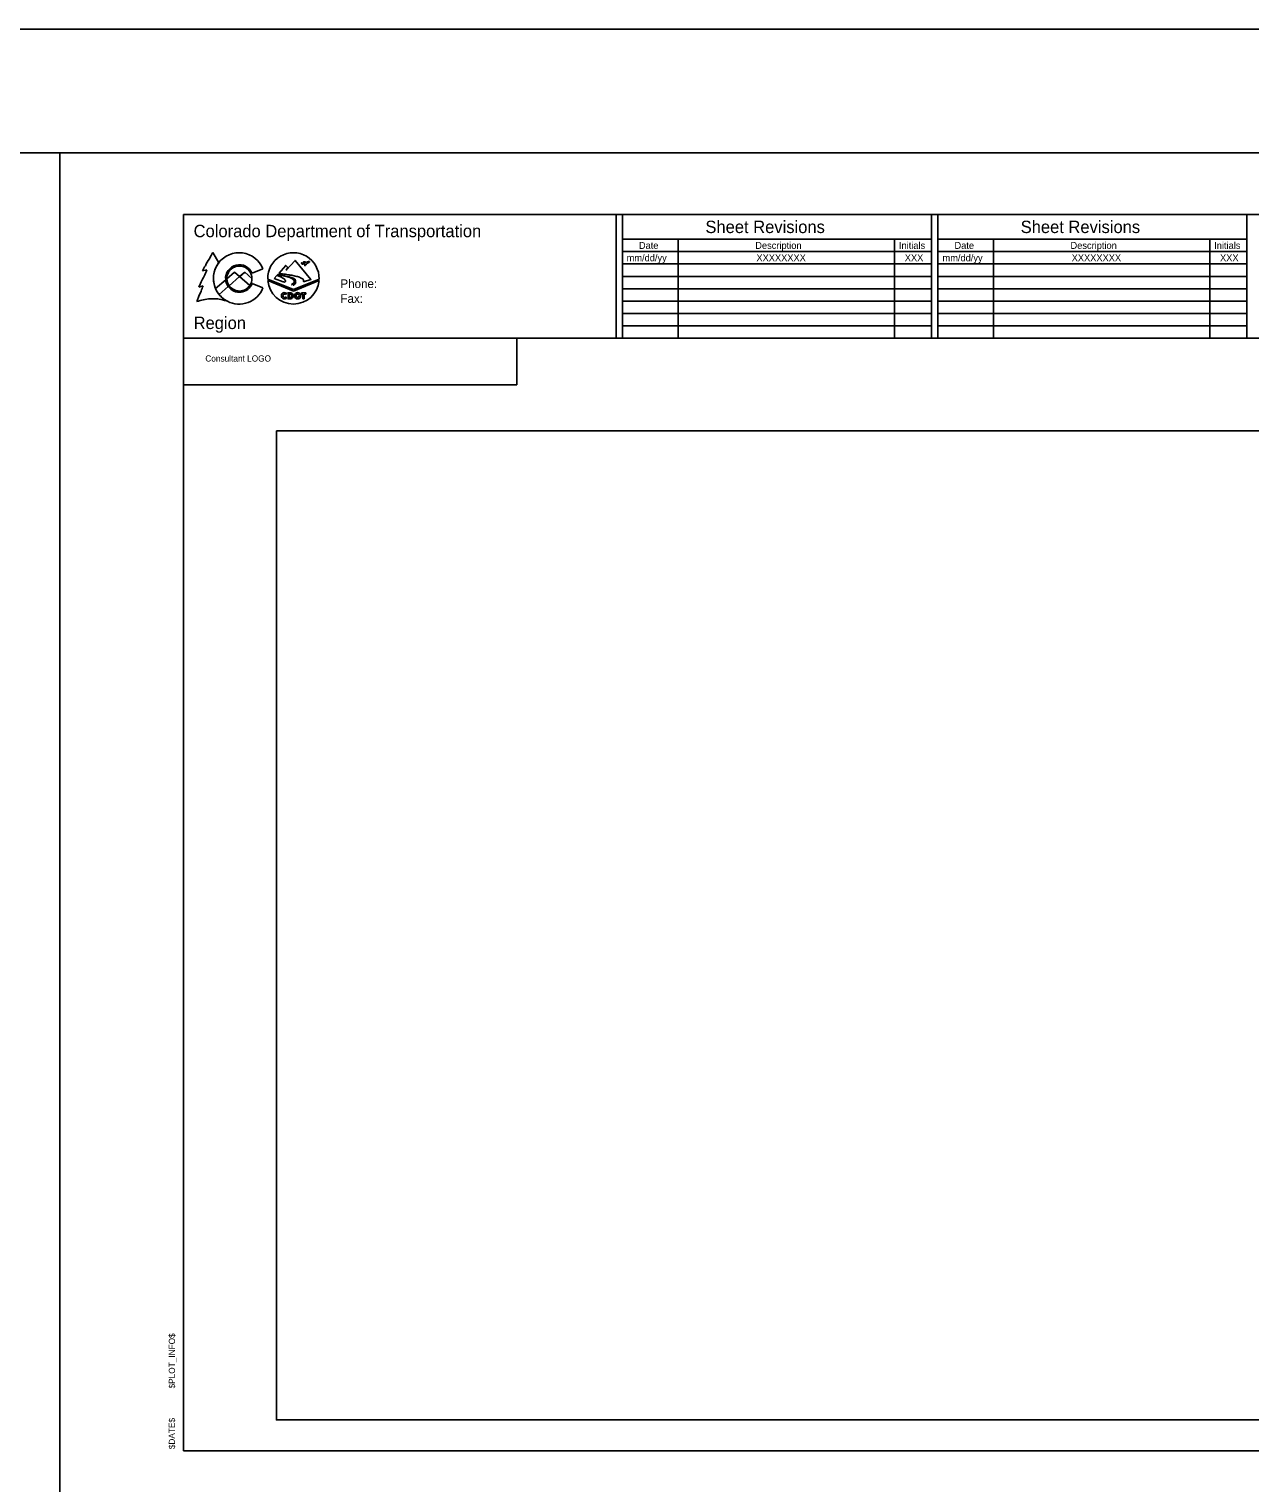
# Model space of a CAD drawing. Extents: x 0 to 3, y 0 to 2.
# Drawn here: x 1.521 to 2.344, y 1.02 to 2 of the extents above; entities that cross this region are included whole.
import ezdxf

# ---------------------------------------------------------------- set-up
doc = ezdxf.new("R2010")
doc.units = 0
for name, color, linetype in [('DRAFT_Information-No Plot', 7, 'Continuous'), ('SHEET_Lines', 7, 'Continuous'), ('SHEET_North Arrow', 7, 'Continuous'), ('SHEET_Plot Boundary', 7, 'Continuous'), ('SHEET_Text-Border Info', 7, 'Continuous')]:
    doc.layers.add(name, color=color, linetype=linetype)

msp = doc.modelspace()

# ---------------------------------------------------------------- linework, layer by layer
at = {"layer": 'DRAFT_Information-No Plot'}
msp.add_line((1.625, 1.79167), (1.625, 1.79167), dxfattribs=at)
msp.add_lwpolyline([(1.6875, 1.72917), (2.85417, 1.72917), (2.85417, 1.0625), (1.6875, 1.0625)], close=True, dxfattribs=at)
at = {"layer": 'SHEET_Lines'}
for p, q in [((1.54167, 1.91667), (1.54167, 0.08333)), ((1.625, 1.79167), (1.625, 1.875)), ((1.625, 1.875), (2.91667, 1.875)), ((1.91667, 1.875), (1.91667, 1.79167)), ((1.92083, 1.875), (1.92083, 1.79167)), ((2.12917, 1.875), (2.12917, 1.79167)), ((2.13333, 1.875), (2.13333, 1.79167)), ((2.34167, 1.875), (2.34167, 1.79167)), ((1.92083, 1.85833), (2.12917, 1.85833)), ((1.95833, 1.79167), (1.95833, 1.85833)), ((2.10417, 1.79167), (2.10417, 1.85833)), ((2.13333, 1.85833), (2.34167, 1.85833)), ((2.17083, 1.79167), (2.17083, 1.85833)), ((2.31667, 1.79167), (2.31667, 1.85833)), ((1.92083, 1.85), (2.12917, 1.85)), ((2.13333, 1.85), (2.34167, 1.85)), ((1.92083, 1.84167), (2.12917, 1.84167)), ((1.92083, 1.83333), (2.12917, 1.83333)), ((2.13333, 1.84167), (2.34167, 1.84167)), ((2.13333, 1.83333), (2.34167, 1.83333)), ((1.92083, 1.825), (2.12917, 1.825)), ((2.13333, 1.825), (2.34167, 1.825)), ((1.92083, 1.81667), (2.12917, 1.81667)), ((2.13333, 1.81667), (2.34167, 1.81667)), ((1.92083, 1.80833), (2.12917, 1.80833)), ((2.13333, 1.80833), (2.34167, 1.80833)), ((1.92083, 1.8), (2.12917, 1.8)), ((2.13333, 1.8), (2.34167, 1.8))]:
    msp.add_line(p, q, dxfattribs=at)
for points in [[(2.95833, 0.08333), (0.125, 0.08333), (0.125, 1.91667), (2.95833, 1.91667)], [(1.625, 1.79167), (1.84959, 1.79167), (1.84959, 1.76025), (1.625, 1.76025)]]:
    msp.add_lwpolyline(points, close=True, dxfattribs=at)
msp.add_lwpolyline([(2.55417, 1.79167), (1.625, 1.79167), (1.625, 1.04167), (2.91667, 1.04167), (2.91667, 1.79167), (2.69167, 1.79167)], dxfattribs=at)
at = {"layer": 'SHEET_Plot Boundary'}
for p, q in [((1.64467, 1.8493), (1.64867, 1.84245)), ((1.64061, 1.83769), (1.63782, 1.83706)), ((1.6593, 1.83614), (1.65414, 1.83166)), ((1.65414, 1.83161), (1.6593, 1.83609)), ((1.66277, 1.83313), (1.6557, 1.827)), ((1.6557, 1.827), (1.66277, 1.83313)), ((1.66277, 1.83313), (1.6593, 1.83614)), ((1.6593, 1.83609), (1.66277, 1.83308)), ((1.66622, 1.83613), (1.66277, 1.83313)), ((1.66277, 1.83308), (1.66622, 1.83608)), ((1.66962, 1.82719), (1.66277, 1.83313)), ((1.66277, 1.83313), (1.66962, 1.82719)), ((1.67104, 1.83194), (1.66622, 1.83613)), ((1.66622, 1.83608), (1.67104, 1.83189)), ((1.67117, 1.83542), (1.67848, 1.83834)), ((1.68606, 1.83182), (1.68788, 1.8339)), ((1.68834, 1.83442), (1.68856, 1.83467)), ((1.70703, 1.84177), (1.70561, 1.84145)), ((1.63818, 1.82697), (1.63533, 1.82609)), ((1.64652, 1.82505), (1.65336, 1.83098)), ((1.65336, 1.83098), (1.64652, 1.82505)), ((1.65507, 1.82645), (1.64891, 1.8211)), ((1.64891, 1.8211), (1.65507, 1.82645)), ((1.67849, 1.82552), (1.67119, 1.82842)), ((1.68172, 1.83148), (1.69902, 1.82442)), ((1.69902, 1.82343), (1.68178, 1.83046)), ((1.69216, 1.82967), (1.68606, 1.83182)), ((1.69808, 1.82766), (1.69773, 1.82781)), ((1.69921, 1.82728), (1.69882, 1.82746)), ((1.69902, 1.82442), (1.71632, 1.83148)), ((1.71627, 1.83046), (1.69902, 1.82343)), ((1.69382, 1.81944), (1.69453, 1.81876)), ((1.69455, 1.82166), (1.69383, 1.82099)), ((1.70451, 1.82135), (1.70451, 1.82223)), ((1.70451, 1.82223), (1.70733, 1.82223)), ((1.70547, 1.82135), (1.70451, 1.82135)), ((1.70547, 1.81812), (1.70547, 1.82135)), ((1.70637, 1.81812), (1.70547, 1.81812)), ((1.70733, 1.82135), (1.70637, 1.82135)), ((1.70637, 1.82135), (1.70637, 1.81812)), ((1.70733, 1.82223), (1.70733, 1.82135))]:
    msp.add_line(p, q, dxfattribs=at)
msp.add_lwpolyline([(0, 2), (3, 2), (3, 0), (0, 0)], close=True, dxfattribs=at)
for points in [[(1.68909, 1.83528), (1.6938, 1.84065), (1.69514, 1.83924), (1.69416, 1.8375), (1.7001, 1.84402), (1.71083, 1.8313), (1.70574, 1.82956)], [(1.69717, 1.81812), (1.6954, 1.81812), (1.6954, 1.82223), (1.69717, 1.82223)], [(1.69694, 1.82136), (1.69632, 1.82136), (1.69632, 1.81901), (1.69694, 1.81901)]]:
    msp.add_lwpolyline(points, dxfattribs=at)
for radius in [0.00212, 0.00114]:
    msp.add_circle((1.70183, 1.82022), radius, dxfattribs=at)
for centre, radius, start, end in [((1.66241, 1.83192), 0.01731, 21.75871, 203.38863), ((1.66243, 1.83193), 0.01732, 142.59022, 242.67381), ((1.69902, 1.83192), 0.01731, 358.51701, 181.48299), ((1.66259, 1.83189), 0.00928, 22.36058, 185.62032), ((1.66259, 1.83184), 0.00845, 0.35858, 181.56098), ((1.66241, 1.83192), 0.01731, 203.38863, 242.71912), ((1.66259, 1.83189), 0.00928, 185.62032, 215.87253), ((1.66259, 1.83189), 0.00845, 181.56098, 215.37659), ((1.66241, 1.83192), 0.01731, 242.71912, 338.26838), ((1.66259, 1.83189), 0.00928, 215.87253, 338.04863), ((1.66259, 1.83189), 0.00845, 215.37659, 326.23275), ((1.66259, 1.83189), 0.00845, 326.23275, 0.35858), ((1.69902, 1.83192), 0.01731, 184.84023, 355.15977), ((1.66243, 1.83193), 0.01732, 218.67794, 242.67381), ((1.66243, 1.83193), 0.01732, 218.67794, 242.67381), ((1.69299, 1.82022), 0.00212, 42.62362, 316.67791), ((1.69299, 1.82022), 0.00114, 42.62362, 316.67791), ((1.69687, 1.82019), 0.00118, 273.22356, 86.77644), ((1.69694, 1.82018), 0.00207, 276.24904, 83.75096)]:
    msp.add_arc(centre, radius, start, end, dxfattribs=at)
for points in [[(1.63782, 1.83706), (1.63965, 1.84048), (1.64234, 1.84523), (1.64467, 1.8493)], [(1.70561, 1.84145), (1.70507, 1.84144), (1.705, 1.84151), (1.7048, 1.84174), (1.70438, 1.84222), (1.70438, 1.84236), (1.70454, 1.84244), (1.70491, 1.84241), (1.70508, 1.84227), (1.70542, 1.84205), (1.70555, 1.84205), (1.70566, 1.84205), (1.70668, 1.84242)], [(1.70668, 1.84242), (1.70611, 1.84267), (1.70588, 1.84278), (1.70571, 1.84291), (1.70579, 1.843), (1.70605, 1.8431), (1.70624, 1.84315), (1.70645, 1.84313), (1.70665, 1.84308), (1.70704, 1.84296), (1.70766, 1.84275)], [(1.70766, 1.84275), (1.7084, 1.84304), (1.70903, 1.84325), (1.7093, 1.84333), (1.70954, 1.84337), (1.70976, 1.84335), (1.70985, 1.84326), (1.70984, 1.84305), (1.70971, 1.84287), (1.70906, 1.84249), (1.70815, 1.84209)], [(1.63533, 1.82609), (1.6364, 1.82856), (1.64015, 1.83645), (1.64061, 1.83769)], [(1.68788, 1.8339), (1.68865, 1.83367), (1.68929, 1.83345), (1.69035, 1.83303), (1.6915, 1.83239), (1.69243, 1.83177), (1.69301, 1.83132), (1.69347, 1.83074), (1.69363, 1.83044), (1.69367, 1.83023), (1.69357, 1.82985), (1.69332, 1.82963), (1.69318, 1.82954), (1.69281, 1.82944), (1.69254, 1.82953), (1.69235, 1.82961), (1.69216, 1.82967)], [(1.68856, 1.83467), (1.69311, 1.83374), (1.69705, 1.83258), (1.69872, 1.83182), (1.69977, 1.83103), (1.70046, 1.83008), (1.7001, 1.82824), (1.69921, 1.82728)], [(1.70574, 1.82956), (1.70596, 1.83017), (1.70565, 1.83114), (1.70374, 1.83241), (1.70099, 1.83333), (1.69787, 1.83401), (1.69554, 1.83442), (1.69162, 1.835), (1.68909, 1.83528)], [(1.70815, 1.84209), (1.70757, 1.84127), (1.70721, 1.84075), (1.7069, 1.84056), (1.7066, 1.84058), (1.70678, 1.8411), (1.70703, 1.84177)], [(1.63393, 1.81626), (1.63483, 1.81866), (1.63677, 1.82341), (1.63818, 1.82697)], [(1.69692, 1.83238), (1.6972, 1.83225), (1.69747, 1.8321), (1.69773, 1.83193), (1.69787, 1.83185), (1.698, 1.83177), (1.69819, 1.83165), (1.69838, 1.83152), (1.69857, 1.83138), (1.69866, 1.83131), (1.69874, 1.83124), (1.69885, 1.83115), (1.699, 1.831), (1.69914, 1.83083), (1.69926, 1.83066), (1.69934, 1.83052), (1.6994, 1.83042), (1.69943, 1.83032), (1.69944, 1.83026), (1.69947, 1.83018), (1.69949, 1.83008), (1.69952, 1.82994), (1.69953, 1.82965), (1.6995, 1.82936), (1.69946, 1.82922), (1.69941, 1.82908), (1.69928, 1.82882), (1.6991, 1.82858), (1.69888, 1.82836), (1.69865, 1.82815), (1.69851, 1.82802), (1.69837, 1.8279), (1.69822, 1.82778), (1.69808, 1.82766)], [(1.69882, 1.82746), (1.69936, 1.8279), (1.69993, 1.82858), (1.70014, 1.82901), (1.70003, 1.83031), (1.69984, 1.83058), (1.69941, 1.831), (1.69808, 1.83189), (1.69692, 1.83238)], [(1.65448, 1.81654), (1.65199, 1.81731), (1.64798, 1.81806), (1.64504, 1.81825), (1.64295, 1.8182), (1.6384, 1.81756), (1.63393, 1.81626)]]:
    msp.add_spline(points, degree=3, dxfattribs=at)
msp.add_open_spline([(1.69773, 1.82781), (1.70238, 1.83093), (1.69521, 1.83319), (1.68834, 1.83442)], degree=2, dxfattribs=at)

# ---------------------------------------------------------------- texts
at = {"layer": 'DRAFT_Information-No Plot'}
msp.add_text('Consultant LOGO', height=0.0041667, dxfattribs=at).set_placement((1.63963, 1.77587))
at = {"layer": 'SHEET_North Arrow'}
for s, height, p in [('Colorado Department of Transportation', 0.0083333, (1.63174, 1.85972)), ('Sheet Revisions', 0.0083333, (1.97672, 1.8625)), ('Sheet Revisions', 0.0083333, (2.18922, 1.8625)), ('Region ', 0.008333, (1.63174, 1.7978))]:
    msp.add_text(s, height=height, dxfattribs=at).set_placement(p)
at = {"layer": 'SHEET_Text-Border Info'}
for s, height, p in [('Date', 0.004667, (1.93189, 1.85183)), ('Description', 0.0046667, (2.01032, 1.85183)), ('Initials', 0.004667, (2.10716, 1.85183)), ('Date', 0.004667, (2.14462, 1.85183)), ('Description', 0.0046667, (2.22282, 1.85183)), ('Initials', 0.004667, (2.31966, 1.85183)), ('mm/dd/yy', 0.004667, (1.92362, 1.8435)), ('XXXXXXXX', 0.004667, (2.01111, 1.8435)), ('XXX', 0.004667, (2.11111, 1.8435)), ('mm/dd/yy', 0.004667, (2.13653, 1.8435)), ('XXXXXXXX', 0.004667, (2.22361, 1.8435)), ('XXX', 0.004667, (2.32361, 1.8435)), ('Phone:', 0.005833, (1.73072, 1.82545)), ('Fax:', 0.005833, (1.73072, 1.81545))]:
    msp.add_text(s, height=height, dxfattribs=at).set_placement(p)
for s, height, p in [('$PLOT_INFO$', 0.0041667, (1.61917, 1.08367)), ('$PLOT_INFO$', 0.0041667, (1.61917, 1.08367)), ('$DATE$', 0.004167, (1.61917, 1.04273)), ('$DATE$', 0.004167, (1.61917, 1.04273))]:
    msp.add_text(s, height=height, rotation=90, dxfattribs=at).set_placement(p)

doc.saveas('drawing.dxf')
